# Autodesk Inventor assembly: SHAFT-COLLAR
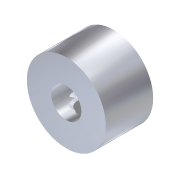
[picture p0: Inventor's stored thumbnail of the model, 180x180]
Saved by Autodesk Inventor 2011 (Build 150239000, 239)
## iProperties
Created: 2007-08
Part Number: SHAFT-COLLAR
Document SubType Name: Assembly
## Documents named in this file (3)
- C:\Data Folder\VEX 2011\Inventor Datasets\Unit 6\Components\SHAFT-COLLAR.iam
- C:\Data Folder\VEX 2011\Inventor Datasets\Unit 6\Components\SHAFT-COLLAR.ipt
- C:\Data Folder\VEX 2011\Inventor Datasets\Unit 6\Components\6-32 SET-SCREW.ipt
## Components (2 placed, 2 different names)
1. SHAFT-COLLAR:1 — Mate:1, Tangent:1, Mate:2
2. 6-32 SET-SCREW:1 — Mate:1, Tangent:1
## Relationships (3: Mate 2, Tangent 1)
- Mate:1: SHAFT-COLLAR:1 ↔ 6-32 SET-SCREW:1
- Tangent:1: SHAFT-COLLAR:1 ↔ 6-32 SET-SCREW:1
- Mate:2: SHAFT-COLLAR:1
